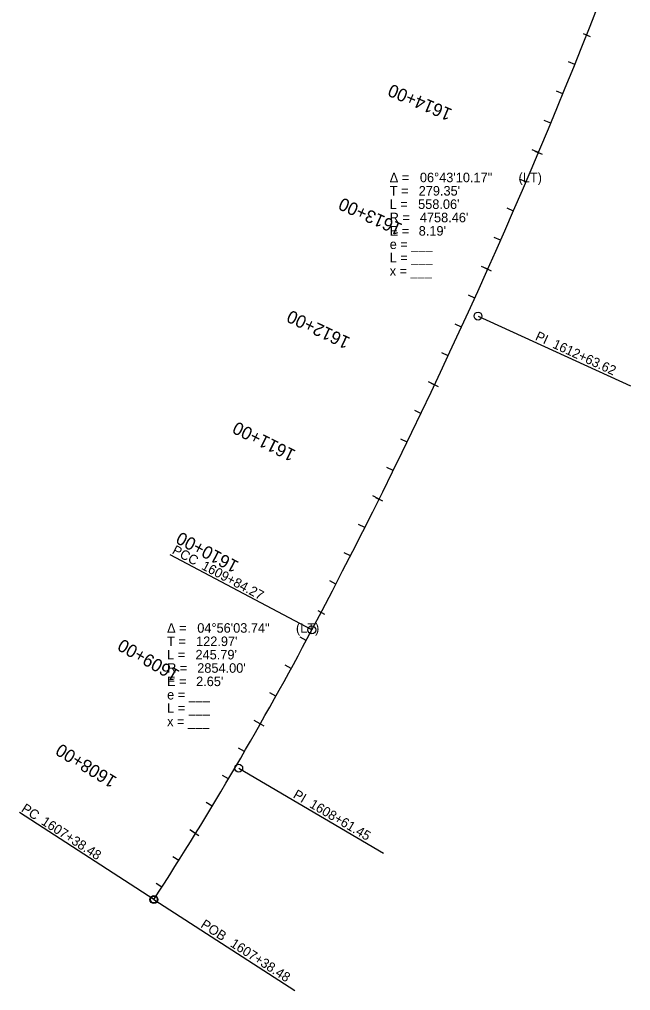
# Model space of a CAD drawing. Extents: x 14119411 to 14122090, y 8669365 to 8673150.
# Drawn here: x 14119411 to 14119892, y 8669365 to 8670129 of the extents above; entities that cross this region are included whole.
import ezdxf

# ---------------------------------------------------------------- set-up
doc = ezdxf.new("R2010")
doc.units = 0
for name, color, linetype in [('Alignment', 7, 'Continuous'), ('Default', 7, 'Continuous'), ('TextAlignment', 7, 'Continuous'), ('TextAlignmentLrg', 7, 'Continuous'), ('TextAlignmentSml', 7, 'Continuous')]:
    doc.layers.add(name, color=color, linetype=linetype)

msp = doc.modelspace()

# ---------------------------------------------------------------- linework, layer by layer
at = {"layer": 'Alignment'}
for centre, radius, start, end in [((14115436.26, 8671875.71), 4758.46, 332.09174, 338.81123), ((14117119.22, 8670984.31), 2854, 327.15737, 332.09174)]:
    msp.add_arc(centre, radius, start, end, dxfattribs=at)
at = {"layer": 'Default'}
msp.add_arc((14115436.26, 8671875.71), 4758.46, 332.09174, 338.81123, dxfattribs=at)
at = {"layer": 'TextAlignment'}
for p, q in [((14119772.05, 8669895.34), (14119892.12, 8669840.5)), ((14119892.12, 8669840.5), (14119892.12, 8669840.5)), ((14119641.3, 8669648.48), (14119529.95, 8669707.45)), ((14119529.95, 8669707.45), (14119529.95, 8669707.45)), ((14119641.3, 8669648.48), (14119529.95, 8669707.45)), ((14119529.95, 8669707.45), (14119529.95, 8669707.45)), ((14119583.74, 8669539.81), (14119697.62, 8669473.06)), ((14119517.05, 8669436.49), (14119411.19, 8669504.83)), ((14119411.19, 8669504.83), (14119411.19, 8669504.83)), ((14119697.62, 8669473.06), (14119697.62, 8669473.06)), ((14119517.05, 8669436.49), (14119627.95, 8669364.9)), ((14119627.95, 8669364.9), (14119627.95, 8669364.9))]:
    msp.add_line(p, q, dxfattribs=at)
for centre, radius in [((14119772.05, 8669895.34), 3.12), ((14119641.3, 8669648.48), 3.12), ((14119641.3, 8669648.48), 3.12), ((14119583.74, 8669539.81), 3.12), ((14119517.05, 8669436.49), 3.12), ((14119517.05, 8669436.49), 2.67)]:
    msp.add_circle(centre, radius, dxfattribs=at)
at = {"layer": 'TextAlignmentLrg'}
for p, q in [((14119854.7, 8670117.53), (14119860.39, 8670115.27)), ((14119819.6, 8670023.88), (14119814.57, 8670026.01)), ((14119779.72, 8669932.18), (14119774.73, 8669934.41)), ((14119737.92, 8669841.34), (14119732.98, 8669843.67)), ((14119694.22, 8669751.4), (14119689.33, 8669753.83)), ((14119645.93, 8669663.81), (14119651.35, 8669660.97)), ((14119600.76, 8669574.6), (14119596.02, 8669577.3)), ((14119549.86, 8669488.53), (14119545.21, 8669491.4))]:
    msp.add_line(p, q, dxfattribs=at)
at = {"layer": 'TextAlignmentSml'}
for p, q in [((14119854.7, 8670117.53), (14119860.39, 8670115.27)), ((14119848.24, 8670093.2), (14119843.18, 8670095.24)), ((14119838.82, 8670070.04), (14119833.76, 8670072.12)), ((14119829.27, 8670046.94), (14119824.23, 8670049.04)), ((14119816.78, 8670025.08), (14119822.42, 8670022.69)), ((14119809.81, 8670000.88), (14119804.79, 8670003.03)), ((14119799.9, 8669977.93), (14119794.89, 8669980.11)), ((14119789.87, 8669955.03), (14119784.87, 8669957.23)), ((14119776.93, 8669933.43), (14119782.51, 8669930.93)), ((14119769.45, 8669909.39), (14119764.48, 8669911.65)), ((14119759.06, 8669886.65), (14119754.1, 8669888.93)), ((14119748.55, 8669863.97), (14119743.6, 8669866.28)), ((14119735.15, 8669842.65), (14119740.69, 8669840.03)), ((14119727.17, 8669818.77), (14119722.25, 8669821.13)), ((14119716.31, 8669796.25), (14119711.39, 8669798.64)), ((14119705.32, 8669773.8), (14119700.42, 8669776.21)), ((14119691.48, 8669752.76), (14119696.96, 8669750.03)), ((14119683, 8669729.06), (14119678.13, 8669731.52)), ((14119671.66, 8669706.77), (14119666.8, 8669709.26)), ((14119660.21, 8669684.55), (14119655.36, 8669687.07)), ((14119645.93, 8669663.81), (14119651.35, 8669660.97)), ((14119636.95, 8669640.29), (14119632.13, 8669642.86)), ((14119625.08, 8669618.29), (14119620.28, 8669620.9)), ((14119613.02, 8669596.39), (14119608.25, 8669599.05)), ((14119598.1, 8669576.11), (14119603.42, 8669573.09)), ((14119588.32, 8669552.92), (14119583.6, 8669555.66)), ((14119575.69, 8669531.34), (14119570.99, 8669534.12)), ((14119562.87, 8669509.88), (14119558.19, 8669512.7)), ((14119547.25, 8669490.14), (14119552.46, 8669486.93)), ((14119536.66, 8669467.3), (14119532.04, 8669470.2)), ((14119523.28, 8669446.18), (14119518.68, 8669449.13))]:
    msp.add_line(p, q, dxfattribs=at)

# ---------------------------------------------------------------- texts
at = {"layer": 'TextAlignment'}
for s, p in [('Δ = ', (14119702.58, 8670000.57)), ('06°43\'10.17"', (14119726.33, 8670000.57)), (' (LT)', (14119801.18, 8670000.57)), ("279.35'", (14119725.39, 8669990.07)), ('T = ', (14119702.58, 8669990.07)), ('L = ', (14119702.58, 8669979.57)), ("558.06'", (14119724.93, 8669979.57)), ('R = ', (14119702.58, 8669969.07)), ("4758.46'", (14119726.29, 8669969.07)), ('E = ', (14119702.58, 8669958.57)), ("8.19'", (14119725.4, 8669958.57)), ('e = ___ ', (14119702.58, 8669948.07)), ('L = ___', (14119702.58, 8669937.57)), ('x = ___', (14119702.58, 8669927.07)), ('04°56\'03.74"', (14119551.16, 8669646.32)), (' (LT)', (14119626.01, 8669646.32)), ('Δ = ', (14119527.41, 8669646.32)), ('T = ', (14119527.41, 8669635.82)), ("122.97'", (14119550.22, 8669635.82)), ('L = ', (14119527.41, 8669625.32)), ("245.79'", (14119549.75, 8669625.32)), ('R = ', (14119527.41, 8669614.82)), ("2854.00'", (14119551.12, 8669614.82)), ('E = ', (14119527.41, 8669604.32)), ("2.65'", (14119550.23, 8669604.32)), ('e = ___ ', (14119527.41, 8669593.82)), ('L = ___', (14119527.41, 8669583.32)), ('x = ___', (14119527.41, 8669572.82))]:
    msp.add_text(s, height=7.5, dxfattribs=at).set_placement(p)
for s, rotation, p in [('PI ', 335.45149, (14119816.52, 8669876.84)), ('1612+63.62', 335.45149, (14119830.11, 8669870.63)), ('PCC', 332.09174, (14119530.72, 8669708.91)), ('PCC', 332.09174, (14119530.72, 8669708.91)), ('1609+84.27', 332.09174, (14119553.9, 8669696.63)), ('1609+84.27', 332.09174, (14119553.9, 8669696.63)), ('PI ', 329.62456, (14119625.95, 8669516.98)), ('PC', 327.15737, (14119412.08, 8669506.21)), ('1608+61.45', 329.62456, (14119638.84, 8669509.42)), ('1607+38.48', 327.15737, (14119427.77, 8669496.08)), ('POB ', 327.15737, (14119553.23, 8669415.1)), ('1607+38.48', 327.15737, (14119576.51, 8669400.07))]:
    msp.add_text(s, height=7.5, rotation=rotation, dxfattribs=at).set_placement(p)
at = {"layer": 'TextAlignmentLrg'}
msp.add_text('1610+00', height=10.02, rotation=152.28115, dxfattribs=at).set_placement((14119584.58, 8669701.71))
at = {"layer": 'TextAlignmentSml'}
for s, rotation, p in [('1614+00', 157.09748, (14119752.46, 8670057.69)), ('1613+00', 155.89339, (14119713.31, 8669967.39)), ('1612+00', 154.68931, (14119672.26, 8669877.93)), ('1611+00', 153.48523, (14119629.34, 8669789.36)), ('1610+00', 152.28115, (14119584.58, 8669701.71)), ('1609+00', 150.39998, (14119538.03, 8669616)), ('1608+00', 148.39242, (14119488.61, 8669532.11))]:
    msp.add_text(s, height=10.02, rotation=rotation, dxfattribs=at).set_placement(p)

doc.saveas('drawing.dxf')
